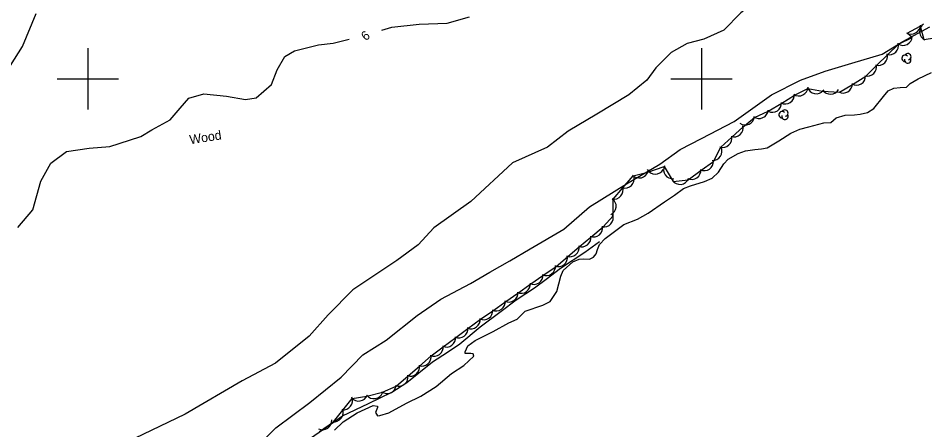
# Model space of a CAD drawing. Extents: x 643342 to 646936, y 5873857 to 5876103.
# Drawn here: x 645577.3 to 645872.9, y 5874285.7 to 5874419.8 of the extents above; entities that cross this region are included whole.
import ezdxf

# ---------------------------------------------------------------- set-up
doc = ezdxf.new("R2010")
doc.units = 0
for name, color, linetype in [('Niveau 2', 7, 'Continuous'), ('Niveau 22', 7, 'Continuous'), ('Niveau 4', 7, 'Continuous'), ('Niveau 44', 7, 'Continuous'), ('Niveau 61', 7, 'Continuous')]:
    doc.layers.add(name, color=color, linetype=linetype)

msp = doc.modelspace()

# ---------------------------------------------------------------- linework, layer by layer
at = {"layer": 'Niveau 2'}
for points in [[(645818.65, 5874426.19), (645812.88, 5874421.58), (645807.31, 5874415.93), (645800.83, 5874412.97), (645795.35, 5874411.51), (645790.21, 5874408.59), (645785.21, 5874403.58), (645782.27, 5874399.6), (645776.34, 5874394.82), (645765.98, 5874388.51), (645756.63, 5874382.98), (645749.83, 5874377.76), (645738.44, 5874372.67), (645724.83, 5874360.04), (645712.81, 5874351.48), (645707.74, 5874345.97)], [(645573.5, 5874402.32), (645578.66, 5874410.52), (645583.18, 5874421.3)], [(645695.85, 5874415.89), (645699.08, 5874416.91), (645708.05, 5874417.88), (645717.18, 5874418.16), (645724.46, 5874420.19)], [(645652.62, 5874277.67), (645661.3, 5874286.37), (645672.39, 5874294.53), (645682.55, 5874302.86), (645689.63, 5874310.16), (645697.22, 5874314.91), (645707.39, 5874322.89), (645715.06, 5874328.23), (645724.71, 5874333.36), (645731.09, 5874337.09), (645737.52, 5874340.76), (645744.24, 5874344.63), (645755.2, 5874351.02), (645763.57, 5874358.29), (645775.63, 5874365.8), (645786.46, 5874372.21), (645793.06, 5874377.01), (645800.09, 5874380.6), (645810.7, 5874386.11), (645822.88, 5874394.81), (645832.35, 5874399.64), (645840.32, 5874402.53), (645849.01, 5874405.12), (645858.92, 5874408.1), (645865.66, 5874412.25), (645874.48, 5874417.03)], [(645582.04, 5874357.35), (645584.69, 5874366.67), (645587.91, 5874372.51), (645593.11, 5874376.38), (645600.47, 5874377.48), (645607.17, 5874377.95), (645610.24, 5874378.92), (645617.34, 5874381.23), (645620.91, 5874383.47), (645626.85, 5874386.69), (645630.08, 5874390.48), (645632.95, 5874393.72), (645637.84, 5874395.17), (645645.2, 5874394.4), (645651.36, 5874393.25), (645654.85, 5874393.9), (645659.85, 5874398.22), (645661.69, 5874402.97), (645664.19, 5874407.3), (645667.43, 5874409.16), (645675.24, 5874411.17), (645679.96, 5874411.67), (645685.22, 5874412.93)], [(645577.18, 5874351.63), (645582.04, 5874357.35)], [(645707.74, 5874345.97), (645700.7, 5874340.84), (645686.44, 5874331.28), (645678.32, 5874323.12), (645672.11, 5874316.17), (645661.21, 5874307.38), (645650.31, 5874301.61), (645631.7, 5874290.81), (645615.26, 5874282.86), (645597.15, 5874271.98), (645580.9, 5874264.51), (645565.6, 5874253.13), (645552.82, 5874245.9), (645538.66, 5874240.21), (645526.24, 5874239.79), (645514.41, 5874239.3), (645505.37, 5874240.36)]]:
    msp.add_lwpolyline(points, dxfattribs=at)
at = {"layer": 'Niveau 22'}
msp.add_lwpolyline([(645672.23, 5874282.71), (645677.13, 5874286.11), (645683.02, 5874290.28), (645691.49, 5874294.28), (645699.15, 5874297.98), (645703.95, 5874301.14), (645712.35, 5874307.83), (645717.26, 5874310.99), (645721.27, 5874313.73), (645727.89, 5874319.24), (645734.77, 5874324.3), (645739.64, 5874328.04), (645745.66, 5874331.98), (645749.43, 5874334.71), (645754.06, 5874338.32), (645762.06, 5874343.53), (645766.75, 5874347.07)], dxfattribs=at)
at = {"layer": 'Niveau 4'}
for points in [[(645750.74, 5874327.47), (645752.86, 5874330.7), (645754.25, 5874335.77), (645754.94, 5874337.6), (645758.15, 5874340.44), (645760.21, 5874341.31), (645761.5, 5874341.4), (645763.52, 5874341.32), (645764.89, 5874341.89), (645765.75, 5874343.02), (645766.11, 5874344.47), (645766.82, 5874346.06), (645768.69, 5874347.97), (645774.72, 5874352.56), (645779.19, 5874354.31), (645782.71, 5874356.23), (645787.98, 5874359.93), (645791.23, 5874362.18), (645794.14, 5874364.29), (645796.44, 5874365.17), (645801.05, 5874366.58), (645803.56, 5874367.71), (645805.54, 5874369.63), (645807.34, 5874372.37), (645808.76, 5874373.89), (645812.05, 5874375.67), (645814.34, 5874376.55), (645817.49, 5874377.02), (645819.6, 5874377.18), (645821.46, 5874377.55), (645825.3, 5874379.85), (645829.12, 5874382.38), (645832.09, 5874383.66), (645834.99, 5874384.35), (645839.96, 5874385.66), (645842.19, 5874385.83), (645843.96, 5874387.38), (645846.85, 5874388.18), (645849.9, 5874388.29), (645851.77, 5874388.55), (645854.21, 5874389.09), (645856.23, 5874390.42), (645859.35, 5874394.31), (645860.87, 5874396.08), (645862.8, 5874397.05), (645864.79, 5874397.19), (645866.9, 5874397.35), (645868.11, 5874398.5), (645870.71, 5874400), (645875.03, 5874402.09)], [(645680.45, 5874285.51), (645683.2, 5874288.32), (645687.84, 5874291.16), (645692.99, 5874293.56), (645694.41, 5874293.43), (645694.45, 5874292.96), (645693.74, 5874291.37), (645694.42, 5874290.23), (645695.24, 5874290.29), (645698.13, 5874291.22), (645703.93, 5874294.38), (645708.61, 5874296.63), (645713.57, 5874299.84), (645718.58, 5874304), (645722.63, 5874306.67), (645725.84, 5874309.63), (645725.66, 5874310.45), (645724.83, 5874310.51), (645723.06, 5874310.49), (645723.01, 5874311.08), (645723.93, 5874313.04), (645726.28, 5874314.75), (645732.09, 5874317.67), (645737.2, 5874320.54), (645739.95, 5874321.69), (645742.58, 5874324.38), (645748.34, 5874326.34), (645750.74, 5874327.47)]]:
    msp.add_lwpolyline(points, dxfattribs=at)
at = {"layer": 'Niveau 44'}
for points in [[(645774.42, 5874364.51), (645777.81, 5874368.43), (645782.51, 5874369.61), (645787.84, 5874371.42), (645790.84, 5874366.63), (645795.67, 5874367.15), (645799.96, 5874370.28), (645803.95, 5874373.05), (645806.38, 5874377.76), (645809.94, 5874381.06), (645813.61, 5874384.45), (645817.36, 5874387.49), (645821.76, 5874389.53), (645826.26, 5874392.08), (645830.33, 5874394.73), (645834.75, 5874396.88), (645839.53, 5874396.03), (645845.07, 5874395.66), (645849.23, 5874398.15), (645853.6, 5874400.95), (645857.07, 5874404.34), (645860.76, 5874407.94), (645864.23, 5874411.33), (645868.68, 5874413.48), (645867.13, 5874414.9), (645871.38, 5874417.25), (645872.55, 5874412.87), (645877.5, 5874413.65)], [(645675.56, 5874285.16), (645680.11, 5874288.29), (645683.12, 5874292.1), (645686.21, 5874295.92), (645691.01, 5874296.68), (645696.04, 5874297.89), (645700.47, 5874299.87), (645704.46, 5874303.23), (645708.13, 5874306.41), (645711.98, 5874309.8), (645715.88, 5874312.69), (645720.01, 5874315.76), (645723.91, 5874318.65), (645728.05, 5874321.69), (645732.02, 5874324.49), (645736.23, 5874327.45), (645740.19, 5874330.25), (645744.4, 5874333.21), (645748.37, 5874336.01), (645752.63, 5874338.94), (645756.34, 5874342.06), (645760.28, 5874345.38), (645763.99, 5874348.5), (645767.99, 5874351.81), (645771.24, 5874355.41), (645771.26, 5874360.83), (645774.42, 5874364.51)]]:
    msp.add_lwpolyline(points, dxfattribs=at)
for centre, radius, start, end in [((645868.4, 5874417.62), 3, 238.9401, 358.918), ((645868.4, 5874417.62), 3, 238.9401, 358.918), ((645868.4, 5874417.62), 3, 238.9401, 358.918), ((645874.13, 5874415.42), 3, 124.364, 244.3419), ((645874.13, 5874415.42), 3, 124.364, 244.3419), ((645874.13, 5874415.42), 3, 124.364, 244.3419), ((645865.71, 5874413.93), 3, 237.3026, 357.2805), ((645865.71, 5874413.93), 3, 237.3026, 357.2805), ((645865.71, 5874413.93), 3, 237.3026, 357.2805), ((645861.26, 5874410.89), 3, 254.3262, 14.3041), ((645861.26, 5874410.89), 3, 254.3262, 14.3041), ((645861.26, 5874410.89), 3, 254.3262, 14.3041), ((645857.68, 5874407.4), 3, 254.3262, 14.3041), ((645857.68, 5874407.4), 3, 254.3262, 14.3041), ((645857.68, 5874407.4), 3, 254.3262, 14.3041), ((645866.4, 5874406.73), 1.05, 44.1154, 269.804), ((645867.3, 5874407.26), 1.05, 282.2692, 149.7263), ((645854.11, 5874403.91), 3, 254.3262, 14.3041), ((645854.11, 5874403.91), 3, 254.3262, 14.3041), ((645854.11, 5874403.91), 3, 254.3262, 14.3041), ((645867.3, 5874406.21), 1.05, 166.9369, 29.6212), ((645846.25, 5874398.42), 3, 240.8891, 0.867), ((645846.25, 5874398.42), 3, 240.8891, 0.867), ((645846.25, 5874398.42), 3, 240.8891, 0.867), ((645850.54, 5874400.98), 3, 240.8891, 0.867), ((645850.54, 5874400.98), 3, 240.8891, 0.867), ((645850.54, 5874400.98), 3, 240.8891, 0.867), ((645831.81, 5874397.48), 3, 236.1124, 356.0904), ((645831.81, 5874397.48), 3, 236.1124, 356.0904), ((645831.81, 5874397.48), 3, 236.1124, 356.0904), ((645837.45, 5874398.19), 3, 199.8381, 319.8161), ((645837.45, 5874398.19), 3, 199.8381, 319.8161), ((645837.45, 5874398.19), 3, 199.8381, 319.8161), ((645842.12, 5874398.02), 3, 211.5435, 331.5214), ((645842.12, 5874398.02), 3, 211.5435, 331.5214), ((645842.12, 5874398.02), 3, 211.5435, 331.5214), ((645823.14, 5874392.16), 3, 243.064, 3.0419), ((645823.14, 5874392.16), 3, 243.064, 3.0419), ((645823.14, 5874392.16), 3, 243.064, 3.0419), ((645827.33, 5874394.88), 3, 243.064, 3.0419), ((645827.33, 5874394.88), 3, 243.064, 3.0419), ((645827.33, 5874394.88), 3, 243.064, 3.0419), ((645818.82, 5874390.11), 3, 234.9393, 354.9173), ((645818.82, 5874390.11), 3, 234.9393, 354.9173), ((645818.82, 5874390.11), 3, 234.9393, 354.9173), ((645826.33, 5874388.34), 1.05, 44.1154, 269.804), ((645827.23, 5874388.87), 1.05, 282.2692, 149.7263), ((645814.28, 5874388), 3, 234.9393, 354.9173), ((645814.28, 5874388), 3, 234.9393, 354.9173), ((645814.28, 5874388), 3, 234.9393, 354.9173), ((645827.23, 5874387.82), 1.05, 166.9369, 29.6212), ((645810.63, 5874384.1), 3, 252.8399, 12.8179), ((645810.63, 5874384.1), 3, 252.8399, 12.8179), ((645810.63, 5874384.1), 3, 252.8399, 12.8179), ((645806.96, 5874380.7), 3, 252.8399, 12.8179), ((645806.96, 5874380.7), 3, 252.8399, 12.8179), ((645806.96, 5874380.7), 3, 252.8399, 12.8179), ((645803.72, 5874376.46), 3, 266.9046, 26.8825), ((645803.72, 5874376.46), 3, 266.9046, 26.8825), ((645803.72, 5874376.46), 3, 266.9046, 26.8825), ((645790.69, 5874370.48), 3, 155.7302, 275.7082), ((645790.69, 5874370.48), 3, 155.7302, 275.7082), ((645790.69, 5874370.48), 3, 155.7302, 275.7082), ((645800.95, 5874373.11), 3, 244.6869, 4.6649), ((645800.95, 5874373.11), 3, 244.6869, 4.6649), ((645800.95, 5874373.11), 3, 244.6869, 4.6649), ((645779.73, 5874370.73), 3, 224.1155, 344.0935), ((645779.73, 5874370.73), 3, 224.1155, 344.0935), ((645779.73, 5874370.73), 3, 224.1155, 344.0935), ((645784.93, 5874371.99), 3, 210.8137, 330.7917), ((645784.93, 5874371.99), 3, 210.8137, 330.7917), ((645784.93, 5874371.99), 3, 210.8137, 330.7917), ((645796.84, 5874370.27), 3, 244.6869, 4.6649), ((645796.84, 5874370.27), 3, 244.6869, 4.6649), ((645796.84, 5874370.27), 3, 244.6869, 4.6649), ((645775.14, 5874367.46), 3, 253.6853, 13.6633), ((645775.14, 5874367.46), 3, 253.6853, 13.6633), ((645775.14, 5874367.46), 3, 253.6853, 13.6633), ((645793.06, 5874368.64), 3, 216.1393, 336.1172), ((645793.06, 5874368.64), 3, 216.1393, 336.1172), ((645793.06, 5874368.64), 3, 216.1393, 336.1172), ((645771.51, 5874363.82), 3, 259.3326, 19.3105), ((645771.51, 5874363.82), 3, 259.3326, 19.3105), ((645771.51, 5874363.82), 3, 259.3326, 19.3105), ((645769.24, 5874358.52), 3, 294.8782, 54.8561), ((645769.24, 5874358.52), 3, 294.8782, 54.8561), ((645769.24, 5874358.52), 3, 294.8782, 54.8561), ((645768.3, 5874354.79), 3, 258.0079, 17.9858), ((645768.3, 5874354.79), 3, 258.0079, 17.9858), ((645768.3, 5874354.79), 3, 258.0079, 17.9858), ((645764.82, 5874351.51), 3, 250.1087, 10.0867), ((645764.82, 5874351.51), 3, 250.1087, 10.0867), ((645764.82, 5874351.51), 3, 250.1087, 10.0867), ((645761, 5874348.29), 3, 250.1087, 10.0867), ((645761, 5874348.29), 3, 250.1087, 10.0867), ((645761, 5874348.29), 3, 250.1087, 10.0867), ((645757.17, 5874345.07), 3, 250.1087, 10.0867), ((645757.17, 5874345.07), 3, 250.1087, 10.0867), ((645757.17, 5874345.07), 3, 250.1087, 10.0867), ((645753.35, 5874341.85), 3, 250.1087, 10.0867), ((645753.35, 5874341.85), 3, 250.1087, 10.0867), ((645753.35, 5874341.85), 3, 250.1087, 10.0867), ((645749.46, 5874338.93), 3, 245.1828, 5.1607), ((645749.46, 5874338.93), 3, 245.1828, 5.1607), ((645749.46, 5874338.93), 3, 245.1828, 5.1607), ((645745.37, 5874336.05), 3, 245.1828, 5.1607), ((645745.37, 5874336.05), 3, 245.1828, 5.1607), ((645745.37, 5874336.05), 3, 245.1828, 5.1607), ((645741.28, 5874333.17), 3, 245.1828, 5.1607), ((645741.28, 5874333.17), 3, 245.1828, 5.1607), ((645741.28, 5874333.17), 3, 245.1828, 5.1607), ((645737.19, 5874330.29), 3, 245.1828, 5.1607), ((645737.19, 5874330.29), 3, 245.1828, 5.1607), ((645737.19, 5874330.29), 3, 245.1828, 5.1607), ((645733.11, 5874327.41), 3, 245.1828, 5.1607), ((645733.11, 5874327.41), 3, 245.1828, 5.1607), ((645733.11, 5874327.41), 3, 245.1828, 5.1607), ((645729.02, 5874324.53), 3, 245.1828, 5.1607), ((645729.02, 5874324.53), 3, 245.1828, 5.1607), ((645729.02, 5874324.53), 3, 245.1828, 5.1607), ((645724.92, 5874321.6), 3, 246.605, 6.5829), ((645724.92, 5874321.6), 3, 246.605, 6.5829), ((645724.92, 5874321.6), 3, 246.605, 6.5829), ((645720.91, 5874318.62), 3, 246.605, 6.5829), ((645720.91, 5874318.62), 3, 246.605, 6.5829), ((645720.91, 5874318.62), 3, 246.605, 6.5829), ((645716.89, 5874315.64), 3, 246.605, 6.5829), ((645716.89, 5874315.64), 3, 246.605, 6.5829), ((645716.89, 5874315.64), 3, 246.605, 6.5829), ((645712.88, 5874312.66), 3, 246.605, 6.5829), ((645712.88, 5874312.66), 3, 246.605, 6.5829), ((645712.88, 5874312.66), 3, 246.605, 6.5829), ((645708.92, 5874309.43), 3, 250.9378, 10.9158), ((645708.92, 5874309.43), 3, 250.9378, 10.9158), ((645708.92, 5874309.43), 3, 250.9378, 10.9158), ((645705.14, 5874306.15), 3, 250.9378, 10.9158), ((645705.14, 5874306.15), 3, 250.9378, 10.9158), ((645705.14, 5874306.15), 3, 250.9378, 10.9158), ((645701.36, 5874302.88), 3, 250.9378, 10.9158), ((645701.36, 5874302.88), 3, 250.9378, 10.9158), ((645701.36, 5874302.88), 3, 250.9378, 10.9158), ((645693.27, 5874298.82), 3, 219.0208, 338.9987), ((645693.27, 5874298.82), 3, 219.0208, 338.9987), ((645693.27, 5874298.82), 3, 219.0208, 338.9987), ((645697.54, 5874300.49), 3, 234.049, 354.0269), ((645697.54, 5874300.49), 3, 234.049, 354.0269), ((645697.54, 5874300.49), 3, 234.049, 354.0269), ((645683.33, 5874295.21), 3, 261.7128, 21.6907), ((645683.33, 5874295.21), 3, 261.7128, 21.6907), ((645683.33, 5874295.21), 3, 261.7128, 21.6907), ((645688.33, 5874298.04), 3, 219.0208, 338.9987), ((645688.33, 5874298.04), 3, 219.0208, 338.9987), ((645688.33, 5874298.04), 3, 219.0208, 338.9987), ((645680.23, 5874291.29), 3, 261.7128, 21.6907), ((645680.23, 5874291.29), 3, 261.7128, 21.6907), ((645680.23, 5874291.29), 3, 261.7128, 21.6907), ((645676.54, 5874288.7), 3, 243.6034, 3.5813), ((645676.54, 5874288.7), 3, 243.6034, 3.5813), ((645676.54, 5874288.7), 3, 243.6034, 3.5813)]:
    msp.add_arc(centre, radius, start, end, dxfattribs=at)
at = {"layer": 'Niveau 61'}
for points in [[(645600, 5874410), (645600, 5874400), (645600, 5874390)], [(645800, 5874410), (645800, 5874400), (645800, 5874390)], [(645590, 5874400), (645600, 5874400), (645610, 5874400)], [(645790, 5874400), (645800, 5874400), (645810, 5874400)]]:
    msp.add_lwpolyline(points, dxfattribs=at)

# ---------------------------------------------------------------- texts
at = {"layer": 'Niveau 2'}
msp.add_text('6', height=3, rotation=37.6228, dxfattribs=at).set_placement((645690.54, 5874412.25))
at = {"layer": 'Niveau 44'}
msp.add_text('Wood', height=3, rotation=8.9405, dxfattribs=at).set_placement((645633.41, 5874378.71))

doc.saveas('drawing.dxf')
